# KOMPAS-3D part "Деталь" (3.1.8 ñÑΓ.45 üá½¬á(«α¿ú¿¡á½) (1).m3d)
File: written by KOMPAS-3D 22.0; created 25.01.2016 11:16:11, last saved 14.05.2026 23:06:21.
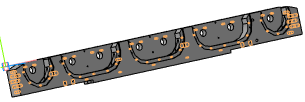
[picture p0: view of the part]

Document properties: Полное имя файла: E:\test_kompas\all_v20\3.1.8 дет.45 Балка(оригинал) (1).m3d

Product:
- Part/product: Деталь
    Масса: 261.985445

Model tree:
1. Эскиз:1
2. Операция выдавливания:1
     Расстояние 1 = 115
3. Эскиз:9  (with: Операция выдавливания:1)
4. Вырезать элемент выдавливания:13
     Расстояние 1 = 115
5. Эскиз:19  (with: Операция выдавливания:1)
6. Вырезать элемент выдавливания:14
     Расстояние 1 = 231
7. Эскиз:20  (with: Операция выдавливания:1)
8. Эскиз:21  (with: Операция выдавливания:1)
9. Вырезать элемент выдавливания:15
     Расстояние 1 = 75
10. Вырезать элемент выдавливания:16
     Расстояние 1 = 10
11. Эскиз:22  (with: Операция выдавливания:1, Вырезать элемент выдавливания:14)
12. Вырезать элемент выдавливания:17
     Расстояние 1 = 30
13. Эскиз:23  (with: Операция выдавливания:1)
14. Вырезать элемент выдавливания:18
     Расстояние 1 = 30
15. Условное изображение резьбы:1  (with: Вырезать элемент выдавливания:17)
     Длина резьбы = 30; Шаг резьбы = 2; Номинальный диаметр резьбы = 20.0651
16. Условное изображение резьбы:2  (with: Вырезать элемент выдавливания:17)
     Длина резьбы = 30; Шаг резьбы = 2; Номинальный диаметр резьбы = 20.0651
17. Условное изображение резьбы:3  (with: Вырезать элемент выдавливания:18)
     Длина резьбы = 30; Шаг резьбы = 2; Номинальный диаметр резьбы = 20.0651
18. Условное изображение резьбы:4  (with: Вырезать элемент выдавливания:18)
     Длина резьбы = 30; Шаг резьбы = 2; Номинальный диаметр резьбы = 20.0651
19. Эскиз:24  (with: Операция выдавливания:1)
20. Вырезать элемент выдавливания:19
     Расстояние 1 = 75
21. Эскиз:25  (with: Операция выдавливания:1)
22. Вырезать элемент выдавливания:20
     Расстояние 1 = 35
23. Условное изображение резьбы:5  (with: Вырезать элемент выдавливания:20)
     Длина резьбы = 35; Шаг резьбы = 1.5; Номинальный диаметр резьбы = 20.0538
24. Условное изображение резьбы:6  (with: Вырезать элемент выдавливания:20)
     Длина резьбы = 35; Шаг резьбы = 1.5; Номинальный диаметр резьбы = 20.0538
25. Условное изображение резьбы:7  (with: Вырезать элемент выдавливания:20)
     Длина резьбы = 35; Шаг резьбы = 1.5; Номинальный диаметр резьбы = 20.0538
26. Условное изображение резьбы:8  (with: Вырезать элемент выдавливания:20)
     Длина резьбы = 35; Шаг резьбы = 1.5; Номинальный диаметр резьбы = 20.0538
27. Условное изображение резьбы:9  (with: Вырезать элемент выдавливания:20)
     Длина резьбы = 35; Шаг резьбы = 1; Номинальный диаметр резьбы = 19.5125
28. Условное изображение резьбы:10  (with: Вырезать элемент выдавливания:20)
     Длина резьбы = 35; Шаг резьбы = 1; Номинальный диаметр резьбы = 19.5125
29. Эскиз:26  (with: Операция выдавливания:1, Вырезать элемент выдавливания:13)
30. Вырезать элемент выдавливания:21
     Расстояние 1 = 35
31. Условное изображение резьбы:11  (with: Вырезать элемент выдавливания:21)
     Длина резьбы = 35; Шаг резьбы = 1.5; Номинальный диаметр резьбы = 20.0538
32. Условное изображение резьбы:12  (with: Вырезать элемент выдавливания:21)
     Длина резьбы = 35; Шаг резьбы = 1.5; Номинальный диаметр резьбы = 20.0538
33. Условное изображение резьбы:13  (with: Вырезать элемент выдавливания:21)
     Длина резьбы = 35; Шаг резьбы = 1.5; Номинальный диаметр резьбы = 20.0538
34. Условное изображение резьбы:14  (with: Вырезать элемент выдавливания:21)
     Длина резьбы = 35; Шаг резьбы = 1.5; Номинальный диаметр резьбы = 20.0538
35. Условное изображение резьбы:15  (with: Вырезать элемент выдавливания:21)
     Длина резьбы = 35; Шаг резьбы = 1.5; Номинальный диаметр резьбы = 20.0538
36. Условное изображение резьбы:16  (with: Вырезать элемент выдавливания:21)
     Длина резьбы = 35; Шаг резьбы = 1.5; Номинальный диаметр резьбы = 20.0538
37. Эскиз:27  (with: Операция выдавливания:1, Вырезать элемент выдавливания:15)
38. Эскиз:28  (with: Операция выдавливания:1)
39. Вырезать элемент выдавливания:22
     Расстояние 1 = 115
40. Эскиз:29  (with: Вырезать элемент выдавливания:16)
41. Вырезать элемент выдавливания:23
     Расстояние 1 = 13
42. Эскиз:30  (with: Вырезать элемент выдавливания:16)
43. Вырезать элемент выдавливания:24
     Расстояние 1 = 13
44. Условное изображение резьбы:17  (with: Вырезать элемент выдавливания:23)
     Длина резьбы = 13; Шаг резьбы = 1; Номинальный диаметр резьбы = 9.51253
45. Условное изображение резьбы:18  (with: Вырезать элемент выдавливания:23)
     Длина резьбы = 13; Шаг резьбы = 1; Номинальный диаметр резьбы = 9.51253
46. Условное изображение резьбы:19  (with: Вырезать элемент выдавливания:23)
     Длина резьбы = 13; Шаг резьбы = 1; Номинальный диаметр резьбы = 9.51253
47. Условное изображение резьбы:20  (with: Вырезать элемент выдавливания:23)
     Длина резьбы = 13; Шаг резьбы = 1; Номинальный диаметр резьбы = 9.51253
48. Условное изображение резьбы:21  (with: Вырезать элемент выдавливания:23)
     Длина резьбы = 13; Шаг резьбы = 1; Номинальный диаметр резьбы = 9.51253
49. Условное изображение резьбы:22  (with: Вырезать элемент выдавливания:24)
     Длина резьбы = 13; Шаг резьбы = 1; Номинальный диаметр резьбы = 9.51253
50. Условное изображение резьбы:23  (with: Вырезать элемент выдавливания:24)
     Длина резьбы = 13; Шаг резьбы = 1; Номинальный диаметр резьбы = 9.51253
51. Условное изображение резьбы:24  (with: Вырезать элемент выдавливания:24)
     Длина резьбы = 13; Шаг резьбы = 1; Номинальный диаметр резьбы = 9.51253
52. Условное изображение резьбы:25  (with: Вырезать элемент выдавливания:24)
     Длина резьбы = 13; Шаг резьбы = 1; Номинальный диаметр резьбы = 9.51253
53. Условное изображение резьбы:26  (with: Вырезать элемент выдавливания:24)
     Длина резьбы = 13; Шаг резьбы = 1; Номинальный диаметр резьбы = 9.51253
54. Эскиз:31  (with: Вырезать элемент выдавливания:16, Вырезать элемент выдавливания:19)
55. Вырезать элемент выдавливания:25
     Расстояние 1 = 13
56. Условное изображение резьбы:27  (with: Вырезать элемент выдавливания:25)
     Длина резьбы = 13; Шаг резьбы = 1; Номинальный диаметр резьбы = 9.51253
57. Условное изображение резьбы:28  (with: Вырезать элемент выдавливания:25)
     Длина резьбы = 13; Шаг резьбы = 1; Номинальный диаметр резьбы = 9.51253
58. Условное изображение резьбы:29  (with: Вырезать элемент выдавливания:25)
     Длина резьбы = 13; Шаг резьбы = 1; Номинальный диаметр резьбы = 9.51253
59. Условное изображение резьбы:30  (with: Вырезать элемент выдавливания:25)
     Длина резьбы = 13; Шаг резьбы = 1; Номинальный диаметр резьбы = 9.51253
60. Условное изображение резьбы:31  (with: Вырезать элемент выдавливания:25)
     Длина резьбы = 13; Шаг резьбы = 1; Номинальный диаметр резьбы = 9.51253
61. Условное изображение резьбы:32  (with: Вырезать элемент выдавливания:25)
     Длина резьбы = 13; Шаг резьбы = 1; Номинальный диаметр резьбы = 9.51253
62. Условное изображение резьбы:33  (with: Вырезать элемент выдавливания:25)
     Длина резьбы = 13; Шаг резьбы = 1; Номинальный диаметр резьбы = 9.51253
63. Эскиз:32  (with: Вырезать элемент выдавливания:16)
64. Вырезать элемент выдавливания:26
     Расстояние 1 = 13
65. Условное изображение резьбы:34  (with: Вырезать элемент выдавливания:26)
     Длина резьбы = 13; Шаг резьбы = 1; Номинальный диаметр резьбы = 9.51253
66. Условное изображение резьбы:35  (with: Вырезать элемент выдавливания:26)
     Длина резьбы = 13; Шаг резьбы = 1; Номинальный диаметр резьбы = 9.51253
67. Условное изображение резьбы:36  (with: Вырезать элемент выдавливания:26)
     Длина резьбы = 13; Шаг резьбы = 1; Номинальный диаметр резьбы = 9.51253
68. Условное изображение резьбы:37  (with: Вырезать элемент выдавливания:26)
     Длина резьбы = 13; Шаг резьбы = 1; Номинальный диаметр резьбы = 9.51253
69. Условное изображение резьбы:38  (with: Вырезать элемент выдавливания:26)
     Длина резьбы = 13; Шаг резьбы = 1; Номинальный диаметр резьбы = 9.51253
70. Условное изображение резьбы:39  (with: Вырезать элемент выдавливания:26)
     Длина резьбы = 13; Шаг резьбы = 1; Номинальный диаметр резьбы = 9.51253
71. Условное изображение резьбы:40  (with: Вырезать элемент выдавливания:26)
     Длина резьбы = 13; Шаг резьбы = 1; Номинальный диаметр резьбы = 9.51253
72. Эскиз:33  (with: Вырезать элемент выдавливания:16)
73. Вырезать элемент выдавливания:27
     Расстояние 1 = 13
74. Условное изображение резьбы:41  (with: Вырезать элемент выдавливания:27)
     Длина резьбы = 13; Шаг резьбы = 1; Номинальный диаметр резьбы = 9.51253
75. Условное изображение резьбы:42  (with: Вырезать элемент выдавливания:27)
     Длина резьбы = 13; Шаг резьбы = 1; Номинальный диаметр резьбы = 9.51253
76. Условное изображение резьбы:43  (with: Вырезать элемент выдавливания:27)
     Длина резьбы = 13; Шаг резьбы = 1; Номинальный диаметр резьбы = 9.51253
77. Условное изображение резьбы:44  (with: Вырезать элемент выдавливания:27)
     Длина резьбы = 13; Шаг резьбы = 1; Номинальный диаметр резьбы = 9.51253
78. Условное изображение резьбы:45  (with: Вырезать элемент выдавливания:27)
     Длина резьбы = 13; Шаг резьбы = 1; Номинальный диаметр резьбы = 9.51253
79. Условное изображение резьбы:46  (with: Вырезать элемент выдавливания:27)
     Длина резьбы = 13; Шаг резьбы = 1; Номинальный диаметр резьбы = 9.51253
80. Условное изображение резьбы:47  (with: Вырезать элемент выдавливания:27)
     Длина резьбы = 13; Шаг резьбы = 1; Номинальный диаметр резьбы = 9.51253
81. Эскиз:34  (with: Операция выдавливания:1)
82. Эскиз:35  (with: Операция выдавливания:1, Вырезать элемент выдавливания:17)
83. Вырезать элемент выдавливания:28
     Расстояние 1 = 94
84. Эскиз:36  (with: Операция выдавливания:1)
85. Вырезать элемент выдавливания:29
     Расстояние 1 = 21
86. Эскиз:37  (with: Вырезать элемент выдавливания:15)
87. Вырезать элемент выдавливания:30
     Расстояние 1 = 40
88. Эскиз:38  (with: Операция выдавливания:1)
89. Вырезать элемент выдавливания:31
     Расстояние 1 = 10
90. Эскиз:39  (with: Операция выдавливания:1)
91. Вырезать элемент выдавливания:32
     Расстояние 1 = 50
92. Условное изображение резьбы:48  (with: Вырезать элемент выдавливания:32)
     Длина резьбы = 50; Шаг резьбы = 1; Номинальный диаметр резьбы = 18.0325
93. Условное изображение резьбы:49  (with: Вырезать элемент выдавливания:32)
     Длина резьбы = 50; Шаг резьбы = 1; Номинальный диаметр резьбы = 18.0325
94. Условное изображение резьбы:50  (with: Вырезать элемент выдавливания:32)
     Длина резьбы = 50; Шаг резьбы = 1; Номинальный диаметр резьбы = 18.0325
95. Условное изображение резьбы:51  (with: Вырезать элемент выдавливания:32)
     Длина резьбы = 50; Шаг резьбы = 1; Номинальный диаметр резьбы = 18.0325
96. Эскиз:40  (with: Операция выдавливания:1, Вырезать элемент выдавливания:13, Вырезать элемент выдавливания:22, Вырезать элемент выдавливания:29)
97. Вырезать элемент выдавливания:33
     Расстояние 1 = 70
98. Условное изображение резьбы:52  (with: Вырезать элемент выдавливания:33)
     Длина резьбы = 70; Шаг резьбы = 1; Номинальный диаметр резьбы = 28.0325
99. Условное изображение резьбы:53  (with: Вырезать элемент выдавливания:33)
     Длина резьбы = 70; Шаг резьбы = 1; Номинальный диаметр резьбы = 28.0325
100. Эскиз:41  (with: Операция выдавливания:1)
101. Вырезать элемент выдавливания:34
     Расстояние 1 = 30
102. Условное изображение резьбы:54  (with: Вырезать элемент выдавливания:34)
     Длина резьбы = 30; Шаг резьбы = 1; Номинальный диаметр резьбы = 8.03253
103. Условное изображение резьбы:55  (with: Вырезать элемент выдавливания:34)
     Длина резьбы = 30; Шаг резьбы = 1; Номинальный диаметр резьбы = 8.03253
104. Условное изображение резьбы:56  (with: Вырезать элемент выдавливания:34)
     Длина резьбы = 30; Шаг резьбы = 1; Номинальный диаметр резьбы = 8.03253
105. Условное изображение резьбы:57  (with: Вырезать элемент выдавливания:34)
     Длина резьбы = 30; Шаг резьбы = 1; Номинальный диаметр резьбы = 8.03253
106. Условное изображение резьбы:58  (with: Вырезать элемент выдавливания:34)
     Длина резьбы = 30; Шаг резьбы = 1; Номинальный диаметр резьбы = 8.03253
107. Вырезать элемент выдавливания:35
     Расстояние 1 = 10
108. Эскиз:42  (with: Операция выдавливания:1, Вырезать элемент выдавливания:33)
109. Вырезать элемент выдавливания:36
     Расстояние 1 = 55
110. Условное изображение резьбы:59  (with: Вырезать элемент выдавливания:36)
     Длина резьбы = 55; Шаг резьбы = 1; Номинальный диаметр резьбы = 16.0325
111. Эскиз:43  (with: Операция выдавливания:1, Вырезать элемент выдавливания:22)
112. Вырезать элемент выдавливания:37
     Расстояние 1 = 30
113. Условное изображение резьбы:60  (with: Вырезать элемент выдавливания:37)
     Длина резьбы = 30; Шаг резьбы = 1; Номинальный диаметр резьбы = 11.0325
114. Условное изображение резьбы:61  (with: Вырезать элемент выдавливания:37)
     Длина резьбы = 30; Шаг резьбы = 1; Номинальный диаметр резьбы = 11.0325
115. Условное изображение резьбы:62  (with: Вырезать элемент выдавливания:37)
     Длина резьбы = 30; Шаг резьбы = 1; Номинальный диаметр резьбы = 11.0325
116. Условное изображение резьбы:63  (with: Вырезать элемент выдавливания:37)
     Длина резьбы = 30; Шаг резьбы = 1; Номинальный диаметр резьбы = 11.0325
117. Условное изображение резьбы:64  (with: Вырезать элемент выдавливания:37)
     Длина резьбы = 30; Шаг резьбы = 1; Номинальный диаметр резьбы = 11.0325
118. Условное изображение резьбы:65  (with: Вырезать элемент выдавливания:37)
     Длина резьбы = 30; Шаг резьбы = 1; Номинальный диаметр резьбы = 11.0325
119. Условное изображение резьбы:66  (with: Вырезать элемент выдавливания:37)
     Длина резьбы = 30; Шаг резьбы = 1; Номинальный диаметр резьбы = 11.0325
120. Условное изображение резьбы:67  (with: Вырезать элемент выдавливания:37)
     Длина резьбы = 30; Шаг резьбы = 1; Номинальный диаметр резьбы = 11.0325
121. Условное изображение резьбы:68  (with: Вырезать элемент выдавливания:37)
     Длина резьбы = 30; Шаг резьбы = 1; Номинальный диаметр резьбы = 11.0325
122. Условное изображение резьбы:69  (with: Вырезать элемент выдавливания:37)
     Длина резьбы = 30; Шаг резьбы = 1; Номинальный диаметр резьбы = 11.0325
123. Условное изображение резьбы:70  (with: Вырезать элемент выдавливания:37)
     Длина резьбы = 30; Шаг резьбы = 1; Номинальный диаметр резьбы = 11.0325
124. Условное изображение резьбы:71  (with: Вырезать элемент выдавливания:37)
     Длина резьбы = 30; Шаг резьбы = 1; Номинальный диаметр резьбы = 11.0325
125. Условное изображение резьбы:72  (with: Вырезать элемент выдавливания:37)
     Длина резьбы = 30; Шаг резьбы = 1; Номинальный диаметр резьбы = 11.0325
126. Условное изображение резьбы:73  (with: Вырезать элемент выдавливания:37)
     Длина резьбы = 30; Шаг резьбы = 1; Номинальный диаметр резьбы = 11.0325
127. Условное изображение резьбы:74  (with: Вырезать элемент выдавливания:37)
     Длина резьбы = 30; Шаг резьбы = 1; Номинальный диаметр резьбы = 11.0325
128. Условное изображение резьбы:75  (with: Вырезать элемент выдавливания:37)  (labels: 4061045924-6285-0-0|0)
     Длина резьбы = 30; Шаг резьбы = 1; Номинальный диаметр резьбы = 11.0325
